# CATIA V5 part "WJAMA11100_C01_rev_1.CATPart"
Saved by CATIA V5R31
Part number: WJAMA11100_C01_rev_1
Source: Unknown
Bounding box of the stored display mesh (mm): x 4191.626 to 4282.551, y -517.8 to -304.615, z 702.6 to 839.864
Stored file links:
  \\solize.local\damia\dept\DDE_Design\10_order\2305701_JAMA_変換検証STEP3_お手本モデル作成\work\02_マツダ_板金\10_CATIA_V5\231211\WJAMA11100_C01_rev_1.CATPart
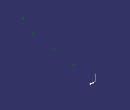
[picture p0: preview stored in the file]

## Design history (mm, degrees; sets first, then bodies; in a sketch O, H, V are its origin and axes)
TTRSSet1
f4a2d38f3ddc11d3a929006094b99c4b_11 "CATTPSSet"
Set1
  Point1 to Point5: stored without definition
Body1 (main body)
